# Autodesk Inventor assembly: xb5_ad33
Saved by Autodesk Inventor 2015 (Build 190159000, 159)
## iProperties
Created: 2018-05
Part Number: xb5_ad33
Checked By: TraceParts S.A.
Catalog Web Link: www.traceparts.com
Document SubType Name: Assembly
Designer: TraceParts
Company: TraceParts S.A.
Author: TraceParts
REFERENCE: XB5 AD33
DESIGN: Control and signalling units Ø 22, Harmony® XB5 plastic, Selector switch with standard handle, Complete units, 3 position stay put, Type of contact 2 "F", Black
SUPPLIER: Schneider Electric
TraceParts.PartNumber: 10-14022008-080708
TraceParts.PartTitle: Control and signalling units Ø 22, Harmony® XB5 plastic, Selector switch with standard handle, Complete units
TraceParts.InstanceId: 10-14022008-080708CDPOYEWXPS4XMJOUSCCWBS2PD
TraceParts.PartStatus: Published
TraceParts.PartVersion: 1.2.3
TRACEPARTS: TRACEPARTS
TraceParts.PartLanguage: en
TraceParts.ClassPath: SCHNEIDER_ELECTRIC:/F_SCHNEIDER/F_TELEMECANIQUE/F_TELEMECANIQUE.04/F_TELEMECANIQUE.04.010/F_TELEMECANIQUE.04.010.020/10-14022008-080708
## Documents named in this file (7)
- C:\TPO v2\SharedFS\Outgoing\xb5_ad33.iam
- C:\TPO v2\SharedFS\Outgoing\xb5_ad33_01.ipt
- C:\TPO v2\SharedFS\Outgoing\xb5_ad33_02.ipt
- C:\TPO v2\SharedFS\Outgoing\xb5_ad33_03.ipt
- C:\TPO v2\SharedFS\Outgoing\xb5_ad33_04.ipt
- C:\TPO v2\SharedFS\Outgoing\xb5_ad33_05.ipt
- C:\TPO v2\SharedFS\Outgoing\xb5_ad33_06.ipt
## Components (6 placed, 6 different names)
1. xb5_ad33_01:1
2. xb5_ad33_02:1
3. xb5_ad33_03:1
4. xb5_ad33_04:1
5. xb5_ad33_05:1
6. xb5_ad33_06:1
